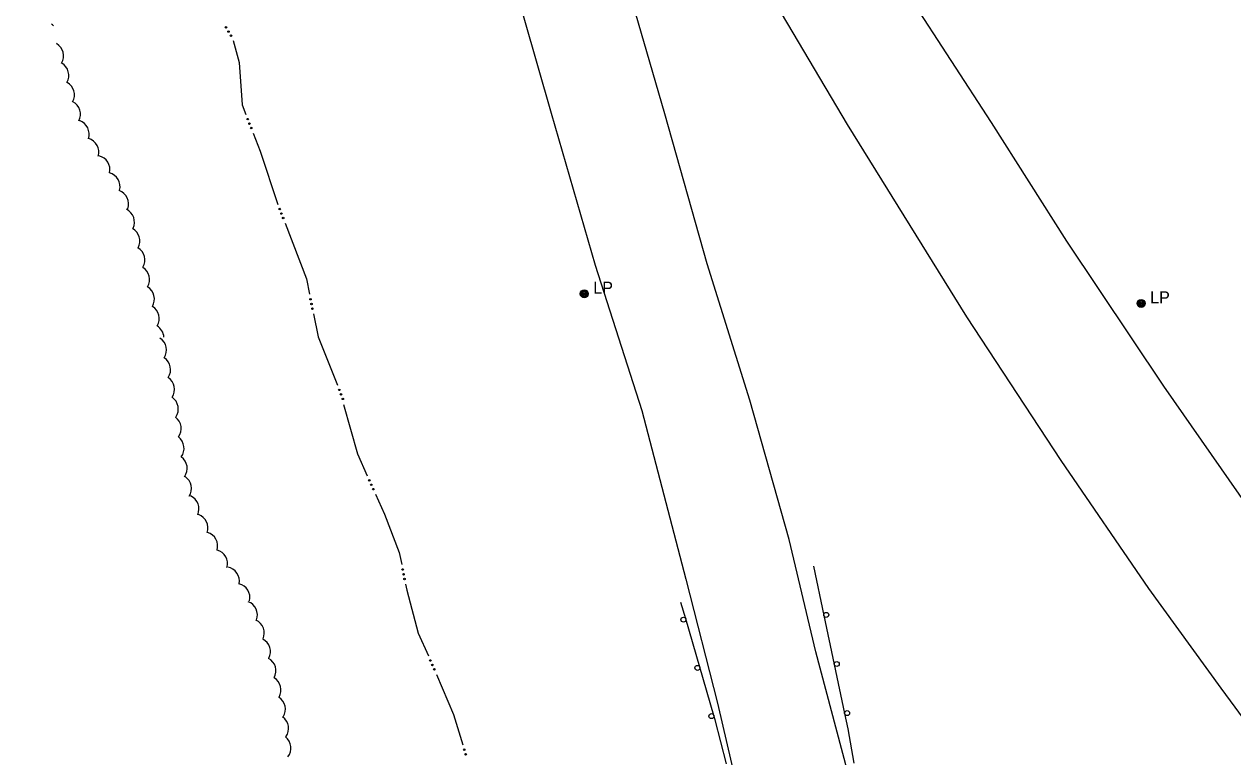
# Model space of a CAD drawing. Extents: x 2402803 to 2427059, y 6985292 to 6997652.
# Drawn here: x 2417088.5 to 2417569.3, y 6992655.1 to 6992946.6 of the extents above; entities that cross this region are included whole.
import ezdxf

# ---------------------------------------------------------------- set-up
doc = ezdxf.new("R2010")
doc.units = 0
for name, color, linetype in [('p_drainage water', 7, 'Continuous'), ('p_road - paved curb', 7, 'Continuous'), ('p_road guard rails', 7, 'Continuous'), ('p_utility manhole', 7, 'Continuous'), ('p_veg woods', 7, 'Continuous')]:
    doc.layers.add(name, color=color, linetype=linetype)

msp = doc.modelspace()

# ---------------------------------------------------------------- linework, layer by layer
at = {"layer": 'p_drainage water'}
for points in [[(2417171.54, 6992940.08), (2417173.97, 6992931.35), (2417175.15, 6992914.54), (2417176.65, 6992910.73)], [(2417179.57, 6992903.29), (2417182.39, 6992896.1), (2417189.41, 6992874.96), (2417189.41, 6992874.95)], [(2417192.27, 6992867.48), (2417200.74, 6992845.34), (2417201.99, 6992839.17)], [(2417203.57, 6992831.33), (2417205.41, 6992822.26), (2417213.08, 6992802.98)], [(2417215.51, 6992795.37), (2417221.07, 6992775.65), (2417224.95, 6992766.97)], [(2417228.22, 6992759.67), (2417231.78, 6992751.7), (2417237.7, 6992736.48), (2417238.64, 6992731.63)], [(2417240.17, 6992723.78), (2417240.63, 6992721.39), (2417245.18, 6992704.38), (2417249.26, 6992695.29)], [(2417252.44, 6992687.95), (2417259.24, 6992671.99), (2417262.94, 6992659.89)]]:
    msp.add_lwpolyline(points, dxfattribs=at)
for centre in [(2417168.77, 6992945.36), (2417169.75, 6992943.71), (2417170.72, 6992942.05), (2417177.38, 6992908.87), (2417178.08, 6992907.08), (2417178.78, 6992905.3), (2417190.13, 6992873.09), (2417190.81, 6992871.29), (2417191.5, 6992869.5), (2417202.38, 6992837.21), (2417202.77, 6992835.33), (2417203.15, 6992833.45), (2417213.82, 6992801.13), (2417214.53, 6992799.34), (2417215.24, 6992797.56), (2417225.77, 6992765.14), (2417226.55, 6992763.39), (2417227.34, 6992761.64), (2417239.02, 6992729.67), (2417239.39, 6992727.78), (2417239.76, 6992725.9), (2417250.07, 6992693.47), (2417250.86, 6992691.71), (2417251.65, 6992689.96), (2417263.52, 6992657.98), (2417264.08, 6992656.14)]:
    msp.add_circle(centre, 0.3, dxfattribs=at)
at = {"layer": 'p_road - paved curb'}
for points in [[(2417088.46, 6993613.89), (2417103.94, 6993560.89), (2417120.5, 6993503.96), (2417139.14, 6993446.01), (2417154.09, 6993396.95), (2417171.41, 6993337.79), (2417185.72, 6993291.03), (2417202.19, 6993236.51), (2417218.9, 6993179.35), (2417236.03, 6993122.86), (2417251.75, 6993068.51), (2417265.84, 6993022.37), (2417281.86, 6992968.28), (2417298.12, 6992911.29), (2417315.59, 6992850.77), (2417334.24, 6992792.96), (2417351.71, 6992725.88), (2417364.28, 6992676.55), (2417377.1, 6992621.07), (2417388.35, 6992567.38), (2417395.29, 6992524.59), (2417397.69, 6992509.02)], [(2417819.74, 6992454.21), (2417784.77, 6992489.79), (2417752.9, 6992525.81), (2417721.01, 6992563.39), (2417684.17, 6992607.23), (2417648.53, 6992652.38), (2417618.99, 6992693.66), (2417575.84, 6992753.94), (2417541.81, 6992802.62), (2417503.28, 6992860.35), (2417473.35, 6992907.5), (2417441.15, 6992956.93), (2417411.5, 6993006.33), (2417387.86, 6993044.95), (2417356.84, 6993104.2), (2417332.19, 6993156.79), (2417302.16, 6993220.68), (2417274.43, 6993285.5), (2417254.86, 6993334.53), (2417228.8, 6993400.57), (2417208, 6993460.78), (2417187.4, 6993522.07), (2417176.03, 6993560.16), (2417161.56, 6993610.84)], [(2417415.83, 6992650.02), (2417403.46, 6992696.93), (2417392.77, 6992741.62), (2417377.18, 6992797), (2417360.13, 6992851.31), (2417343.35, 6992911), (2417326.93, 6992967.72), (2417308.18, 6993032.99), (2417294.29, 6993079.45), (2417281.37, 6993121.57), (2417270.03, 6993160.61), (2417280.13, 6993164.89), (2417295.96, 6993131.65), (2417308.13, 6993105.19), (2417331.13, 6993057.33), (2417356.28, 6993011.02), (2417383.24, 6992961.87), (2417415.93, 6992906.77), (2417415.93, 6992906.77), (2417463.32, 6992830.21), (2417500.81, 6992773.06), (2417535.73, 6992722.12), (2417564.57, 6992682.46), (2417598.64, 6992636.22)]]:
    msp.add_lwpolyline(points, dxfattribs=at)
at = {"layer": 'p_road guard rails'}
for p, q in [((2417402.42, 6992730.96), (2417406.57, 6992711.41)), ((2417351.67, 6992710), (2417349.75, 6992716.61)), ((2417406.57, 6992711.41), (2417410.72, 6992691.86)), ((2417357.25, 6992690.81), (2417351.67, 6992710)), ((2417362.83, 6992671.62), (2417357.25, 6992690.81)), ((2417410.72, 6992691.86), (2417414.87, 6992672.32))]:
    msp.add_line(p, q, dxfattribs=at)
for points in [[(2417367.93, 6992652.29), (2417363.34, 6992669.87), (2417362.83, 6992671.62)], [(2417414.87, 6992672.32), (2417416.14, 6992666.33), (2417418.58, 6992652.67)]]:
    msp.add_lwpolyline(points, dxfattribs=at)
for centre in [(2417407.55, 6992711.62), (2417350.71, 6992709.72), (2417411.7, 6992692.07), (2417356.29, 6992690.53), (2417415.85, 6992672.52), (2417361.87, 6992671.34)]:
    msp.add_circle(centre, 1, dxfattribs=at)
at = {"layer": 'p_utility manhole'}
for centre, radius in [((2417311.27, 6992839.37), 1.6), ((2417311.27, 6992839.37), 1.3), ((2417311.27, 6992839.37), 1), ((2417311.27, 6992839.37), 0.539), ((2417311.27, 6992839.37), 0.192), ((2417532.82, 6992835.54), 1.6), ((2417532.82, 6992835.54), 1.3), ((2417532.82, 6992835.54), 1), ((2417532.82, 6992835.54), 0.539), ((2417532.82, 6992835.54), 0.192)]:
    msp.add_circle(centre, radius, dxfattribs=at)
at = {"layer": 'p_veg woods'}
for centre, start, end in [((2417096.4, 6992941.78), 48.5416, 59.2379), ((2417098.45, 6992934.02), 329.6095, 59.6095), ((2417100.56, 6992926.27), 330.0934, 60.0934), ((2417102.8, 6992918.52), 330.9943, 60.9943), ((2417105.19, 6992910.8), 332.2114, 62.2114), ((2417108.66, 6992902.92), 341.0573, 71.0573), ((2417112.51, 6992895.72), 343.4559, 73.4559), ((2417116.91, 6992888.76), 346.8127, 76.8127), ((2417120.97, 6992881.98), 345.4294, 75.4294), ((2417124.36, 6992875.08), 340.8645, 70.8645), ((2417126.68, 6992867.91), 333.9431, 63.9431), ((2417128.83, 6992860.39), 331.3597, 61.3597), ((2417130.83, 6992852.75), 329.8816, 59.8816), ((2417132.71, 6992845.05), 328.8056, 58.8056), ((2417134.62, 6992837.28), 328.8056, 58.8056), ((2417136.54, 6992829.51), 328.8634, 58.8634), ((2417138.4, 6992821.76), 3.3508, 58.5579), ((2417139.44, 6992816.94), 327.4451, 57.4451), ((2417141.07, 6992809.15), 326.9126, 56.9126), ((2417142.59, 6992801.34), 326.2049, 56.2049), ((2417144.12, 6992793.51), 325.8764, 55.8764), ((2417145.29, 6992785.76), 323.5468, 53.5468), ((2417146.42, 6992777.87), 323.204, 53.204), ((2417147.66, 6992769.91), 323.9966, 53.9966), ((2417149.37, 6992761.89), 326.8413, 56.8413), ((2417152.34, 6992753.8), 335.4892, 65.4892), ((2417155.89, 6992746.25), 340.3745, 70.3745), ((2417159.78, 6992739.03), 343.2682, 73.2682), ((2417163.67, 6992732), 343.8011, 73.8011), ((2417168.41, 6992725.06), 349.5012, 79.5012), ((2417172.62, 6992718.48), 346.882, 76.882), ((2417175.58, 6992711.58), 339.4975, 69.4975), ((2417178.34, 6992704.36), 335.6761, 65.6761), ((2417180.79, 6992696.94), 332.9845, 62.9845), ((2417182.96, 6992689.37), 331.1652, 61.1652), ((2417184.99, 6992681.76), 329.4733, 59.4733), ((2417186.73, 6992674.09), 327.4424, 57.4424), ((2417188, 6992666.4), 324.484, 54.484), ((2417188.91, 6992658.63), 321.9294, 51.9294)]:
    msp.add_arc(centre, 5.65, start, end, dxfattribs=at)

# ---------------------------------------------------------------- texts
at = {"layer": 'p_utility manhole'}
for p in [(2417311.27, 6992839.37), (2417532.82, 6992835.54)]:
    msp.add_text('  LP', height=4.8, dxfattribs=at).set_placement(p)

doc.saveas('drawing.dxf')
